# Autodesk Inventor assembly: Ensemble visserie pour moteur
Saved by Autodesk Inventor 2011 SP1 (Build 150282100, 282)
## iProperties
Created: 2010-12
Part Number: Ensemble visserie pour moteur
Document SubType Name: Assembly
Designer: eric
Author: eric
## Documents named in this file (4)
- D:\eduinventor\maquettesaip2011\machineàpain\Workspace\Ensemble visserie pour moteur.iam
- D:\eduinventor\maquettesaip2011\machineàpain\Workspace\vis M4x10.ipt
- D:\eduinventor\maquettesaip2011\machineàpain\Workspace\Rondelle, W 4.ipt
- D:\eduinventor\maquettesaip2011\machineàpain\Workspace\rondelle  Z4.ipt
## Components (3 placed, 3 different names)
1. vis M4x10:1
2. Rondelle, W 4:1
3. rondelle  Z4:1
